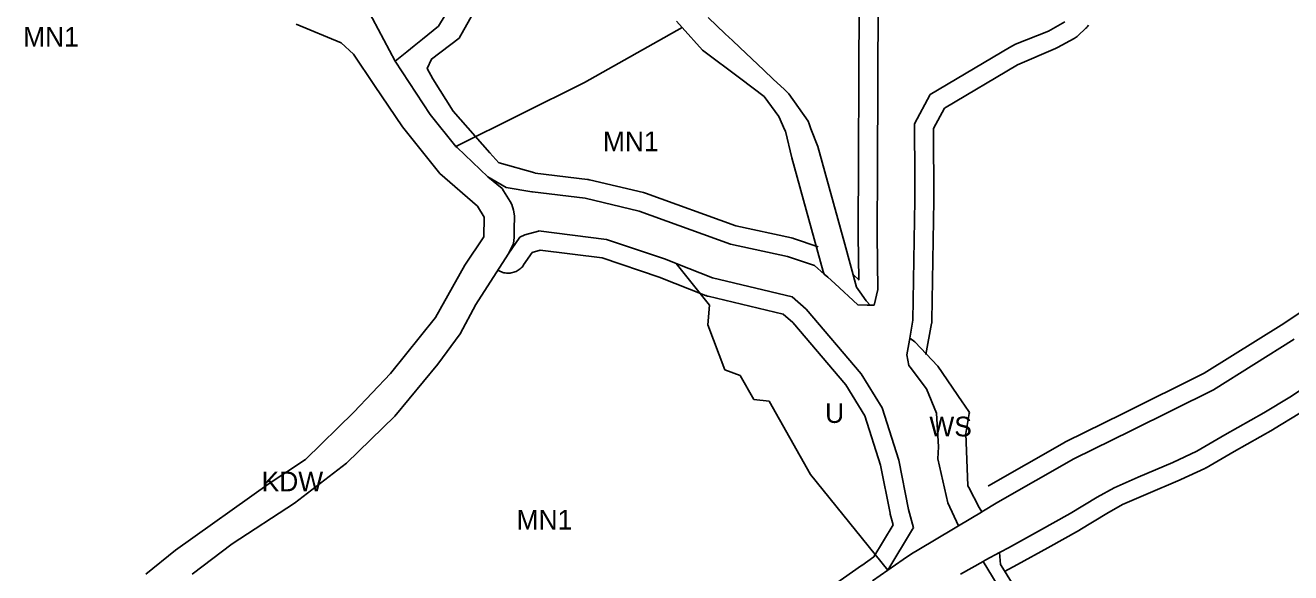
# Model space of a CAD drawing. Extents: x 7435758 to 7439981, y 5550649 to 5554049.
# Drawn here: x 7437108.7 to 7437442.5, y 5551598.7 to 5551743.2 of the extents above; entities that cross this region are included whole.
import ezdxf

# ---------------------------------------------------------------- set-up
doc = ezdxf.new("R2010")
doc.units = 0
for name, color, linetype in [('linie_rozgraniczające', 7, 'Continuous'), ('linie_zabudowy_nieprzekraczalne', 7, 'Continuous'), ('oznaczenia_przeznaczen', 7, 'Continuous')]:
    doc.layers.add(name, color=color, linetype=linetype)

msp = doc.modelspace()

# ---------------------------------------------------------------- linework, layer by layer
at = {"layer": 'linie_rozgraniczające'}
for p, q in [((7437198.86, 5551747.75), (7437206.28, 5551733.7)), ((7437217.69, 5551742.95), (7437221.24, 5551748.69)), ((7437333.66, 5551749.77), (7437333.45, 5551705.87)), ((7437293.36, 5551740.92), (7437288.8, 5551745.24)), ((7437180.18, 5551743.49), (7437192.05, 5551738.53)), ((7437213.5, 5551739.48), (7437217.69, 5551742.95)), ((7437256.26, 5551728.09), (7437281.97, 5551742.54)), ((7437280.47, 5551744.21), (7437281.97, 5551742.54)), ((7437281.97, 5551742.54), (7437287.32, 5551736.59)), ((7437369.87, 5551738.15), (7437378.55, 5551741.64)), ((7437378.55, 5551741.64), (7437382.91, 5551744.04)), ((7437192.05, 5551738.53), (7437195.28, 5551735.55)), ((7437209.36, 5551736.12), (7437211.34, 5551737.73)), ((7437211.34, 5551737.73), (7437213.5, 5551739.48)), ((7437295.25, 5551739.13), (7437293.36, 5551740.92)), ((7437297.16, 5551737.33), (7437295.25, 5551739.13)), ((7437368.28, 5551737.25), (7437369.87, 5551738.15)), ((7437195.28, 5551735.55), (7437200.81, 5551727.22)), ((7437206.28, 5551733.7), (7437209.36, 5551736.12)), ((7437287.32, 5551736.59), (7437297.41, 5551729.02)), ((7437303.53, 5551731.3), (7437297.16, 5551737.33)), ((7437347.38, 5551724.87), (7437368.28, 5551737.25)), ((7437206.28, 5551733.7), (7437215.51, 5551719.65)), ((7437306, 5551728.97), (7437303.53, 5551731.3)), ((7437222.33, 5551711.2), (7437256.26, 5551728.09)), ((7437297.41, 5551729.02), (7437303.64, 5551724.33)), ((7437308.95, 5551726.17), (7437306, 5551728.97)), ((7437200.81, 5551727.22), (7437208.25, 5551716.37)), ((7437310.1, 5551725.09), (7437308.95, 5551726.17)), ((7437315.18, 5551717.81), (7437310.1, 5551725.09)), ((7437343.26, 5551717.18), (7437347.38, 5551724.87)), ((7437303.64, 5551724.33), (7437307.51, 5551719.07)), ((7437215.51, 5551719.65), (7437222.33, 5551711.2)), ((7437307.51, 5551719.07), (7437309.08, 5551715.51)), ((7437315.44, 5551717.16), (7437315.18, 5551717.81)), ((7437208.25, 5551716.37), (7437218.08, 5551704.06)), ((7437309.08, 5551715.51), (7437309.23, 5551715.18)), ((7437309.23, 5551715.18), (7437310.86, 5551708.2)), ((7437315.94, 5551715.86), (7437315.44, 5551717.16)), ((7437317.77, 5551711.13), (7437315.94, 5551715.86)), ((7437343.34, 5551702.98), (7437343.26, 5551717.18)), ((7437222.6, 5551710.86), (7437222.33, 5551711.2)), ((7437324.84, 5551685.4), (7437317.77, 5551711.13)), ((7437230.7, 5551703.15), (7437222.6, 5551710.86)), ((7437310.86, 5551708.2), (7437319.17, 5551678.19)), ((7437333.45, 5551705.87), (7437333.36, 5551687.76)), ((7437218.08, 5551704.06), (7437228.03, 5551695.39)), ((7437230.7, 5551703.15), (7437234.49, 5551700.1)), ((7437235.52, 5551700.32), (7437230.7, 5551703.15)), ((7437343.37, 5551696.97), (7437343.34, 5551702.98)), ((7437234.49, 5551700.1), (7437234.89, 5551699.5)), ((7437234.89, 5551699.5), (7437236.62, 5551696.62)), ((7437242.31, 5551699.24), (7437235.52, 5551700.32)), ((7437242.54, 5551699.2), (7437242.31, 5551699.24)), ((7437256.39, 5551697.51), (7437242.54, 5551699.2)), ((7437228.03, 5551695.39), (7437229.76, 5551692.5)), ((7437236.62, 5551696.62), (7437237.02, 5551695.86)), ((7437237.02, 5551695.86), (7437237.53, 5551694.38)), ((7437237.53, 5551694.38), (7437237.75, 5551692.83)), ((7437270.65, 5551694.13), (7437256.39, 5551697.51)), ((7437342.85, 5551665.33), (7437343.37, 5551696.97)), ((7437229.76, 5551692.5), (7437229.66, 5551687.29)), ((7437237.76, 5551692.35), (7437237.71, 5551689.79)), ((7437237.75, 5551692.83), (7437237.76, 5551692.35)), ((7437294.72, 5551685.4), (7437270.65, 5551694.13)), ((7437237.71, 5551689.79), (7437237.66, 5551687.14)), ((7437239.19, 5551687.25), (7437240.52, 5551687.83)), ((7437240.52, 5551687.83), (7437244.05, 5551688.87)), ((7437244.05, 5551688.87), (7437244.09, 5551688.88)), ((7437244.09, 5551688.88), (7437262.03, 5551686.67)), ((7437333.36, 5551687.76), (7437333.6, 5551673.42)), ((7437229.66, 5551687.29), (7437224.64, 5551679.82)), ((7437236.06, 5551682.75), (7437239.19, 5551687.25)), ((7437237.47, 5551685.53), (7437236.06, 5551682.75)), ((7437237.66, 5551687.14), (7437237.47, 5551685.53)), ((7437262.03, 5551686.67), (7437277.6, 5551681.43)), ((7437309.75, 5551682.17), (7437294.72, 5551685.4)), ((7437327.95, 5551674.09), (7437324.84, 5551685.4)), ((7437227.53, 5551669.44), (7437236.06, 5551682.75)), ((7437277.6, 5551681.43), (7437280.43, 5551680.31)), ((7437316.85, 5551679.75), (7437309.75, 5551682.17)), ((7437224.64, 5551679.82), (7437216.9, 5551666.02)), ((7437280.43, 5551680.31), (7437289.18, 5551669.33)), ((7437280.43, 5551680.31), (7437289.99, 5551676.51)), ((7437319.46, 5551677.45), (7437316.85, 5551679.75)), ((7437319.17, 5551678.19), (7437319.46, 5551677.45)), ((7437289.99, 5551676.51), (7437310.98, 5551671.49)), ((7437319.46, 5551677.45), (7437320.36, 5551676.65)), ((7437320.36, 5551676.65), (7437322.24, 5551675)), ((7437322.24, 5551675), (7437328.34, 5551669.37)), ((7437310.98, 5551671.49), (7437314.72, 5551668.25)), ((7437328.86, 5551672.79), (7437327.95, 5551674.09)), ((7437330.51, 5551670.46), (7437328.86, 5551672.79)), ((7437333.6, 5551673.42), (7437332.64, 5551669.32)), ((7437223.43, 5551661.75), (7437227.53, 5551669.44)), ((7437289.18, 5551669.33), (7437288.76, 5551664.07)), ((7437314.72, 5551668.25), (7437329.19, 5551651.22)), ((7437328.34, 5551669.37), (7437330.77, 5551669.34)), ((7437331.52, 5551669.33), (7437330.51, 5551670.46)), ((7437330.77, 5551669.34), (7437331.52, 5551669.33)), ((7437332.64, 5551669.32), (7437331.52, 5551669.33)), ((7437216.9, 5551666.02), (7437205.05, 5551651.28)), ((7437341.98, 5551660.56), (7437342.85, 5551665.33)), ((7437217.53, 5551653.73), (7437223.43, 5551661.75)), ((7437288.76, 5551664.07), (7437293.23, 5551652.27)), ((7437341.89, 5551660.07), (7437341.19, 5551656.23)), ((7437341.98, 5551660.56), (7437341.89, 5551660.07)), ((7437343.36, 5551659.6), (7437341.98, 5551660.56)), ((7437349.43, 5551653.22), (7437343.36, 5551659.6)), ((7437443.4, 5551660.3), (7437422.12, 5551647)), ((7437341.19, 5551656.23), (7437341.73, 5551653.37)), ((7437205.05, 5551651.28), (7437195.36, 5551641.03)), ((7437206.16, 5551640.05), (7437217.53, 5551653.73)), ((7437293.23, 5551652.27), (7437297.28, 5551650.76)), ((7437329.19, 5551651.22), (7437334.75, 5551642.19)), ((7437341.73, 5551653.37), (7437342.07, 5551652.93)), ((7437342.07, 5551652.93), (7437342.09, 5551652.9)), ((7437342.09, 5551652.9), (7437346.45, 5551647.18)), ((7437355.85, 5551643.78), (7437349.43, 5551653.22)), ((7437442.25, 5551645.05), (7437455.22, 5551653.73)), ((7437297.28, 5551650.76), (7437300.9, 5551644.39)), ((7437300.9, 5551644.39), (7437304.91, 5551643.93)), ((7437346.45, 5551647.18), (7437349.04, 5551640.83)), ((7437422.12, 5551647), (7437400.48, 5551636.23)), ((7437435.36, 5551640.86), (7437442.25, 5551645.05)), ((7437195.36, 5551641.03), (7437182.64, 5551628.59)), ((7437304.91, 5551643.93), (7437315.78, 5551624.62)), ((7437334.75, 5551642.19), (7437339.15, 5551628.36)), ((7437356.44, 5551642.91), (7437355.85, 5551643.78)), ((7437357.73, 5551641.02), (7437356.44, 5551642.91)), ((7437357.68, 5551640.73), (7437357.73, 5551641.02)), ((7437193.44, 5551627.6), (7437206.16, 5551640.05)), ((7437349.04, 5551640.83), (7437349.58, 5551631.89)), ((7437356.75, 5551635.42), (7437357.68, 5551640.73)), ((7437425.1, 5551635.06), (7437435.36, 5551640.86)), ((7437357.3, 5551621.65), (7437356.75, 5551635.42)), ((7437400.48, 5551636.23), (7437385.3, 5551628.76)), ((7437417.69, 5551630.74), (7437425.1, 5551635.06)), ((7437349.58, 5551631.89), (7437349.38, 5551628.79)), ((7437182.64, 5551628.59), (7437173.04, 5551622.24)), ((7437179.73, 5551617.06), (7437193.44, 5551627.6)), ((7437339.15, 5551628.36), (7437341.71, 5551615.37)), ((7437349.38, 5551628.79), (7437352.01, 5551617.11)), ((7437385.3, 5551628.76), (7437365.21, 5551617.29)), ((7437402.23, 5551623.95), (7437411.37, 5551627.82)), ((7437411.37, 5551627.82), (7437417.69, 5551630.74)), ((7437315.78, 5551624.62), (7437336.26, 5551599.38)), ((7437173.04, 5551622.24), (7437148.34, 5551604.64)), ((7437357.55, 5551621.19), (7437357.3, 5551621.65)), ((7437360.31, 5551615.9), (7437357.55, 5551621.19)), ((7437391.43, 5551618.66), (7437395.88, 5551621.14)), ((7437395.88, 5551621.14), (7437402.23, 5551623.95)), ((7437384.27, 5551614.31), (7437391.43, 5551618.66)), ((7437163.32, 5551606.28), (7437179.73, 5551617.06)), ((7437341.71, 5551615.37), (7437342.95, 5551610.56)), ((7437352.01, 5551617.11), (7437354.83, 5551611.09)), ((7437354.83, 5551611.09), (7437360.88, 5551614.71)), ((7437361.02, 5551614.79), (7437360.31, 5551615.9)), ((7437360.88, 5551614.71), (7437361.02, 5551614.79)), ((7437365.21, 5551617.29), (7437361.02, 5551614.79)), ((7437375.99, 5551609.64), (7437384.27, 5551614.31)), ((7437353.54, 5551610.32), (7437354.83, 5551611.09)), ((7437342.73, 5551610.16), (7437336.26, 5551599.38)), ((7437342.95, 5551610.56), (7437342.73, 5551610.16)), ((7437344.42, 5551604.87), (7437353.54, 5551610.32)), ((7437368.02, 5551605.29), (7437375.99, 5551609.64)), ((7437148.34, 5551604.64), (7437140.56, 5551598.36)), ((7437152.75, 5551598.33), (7437163.32, 5551606.28)), ((7437342.42, 5551603.68), (7437344.42, 5551604.87)), ((7437365.64, 5551604.02), (7437366.06, 5551604.25)), ((7437366.06, 5551604.25), (7437368.02, 5551605.29)), ((7437336.26, 5551599.38), (7437340.3, 5551602.2)), ((7437340.3, 5551602.2), (7437342.42, 5551603.68)), ((7437355.37, 5551598.35), (7437361.33, 5551601.7)), ((7437361.88, 5551602.01), (7437361.33, 5551601.7)), ((7437361.33, 5551601.7), (7437366.52, 5551593.17)), ((7437362.07, 5551602.11), (7437361.88, 5551602.01)), ((7437365.63, 5551604.02), (7437362.07, 5551602.11)), ((7437365.89, 5551600.84), (7437365.63, 5551604.02)), ((7437365.63, 5551604.02), (7437365.64, 5551604.02)), ((7437336.26, 5551599.38), (7437332.17, 5551596.54)), ((7437366.07, 5551600.57), (7437365.89, 5551600.84)), ((7437379.39, 5551579.55), (7437366.07, 5551600.57))]:
    msp.add_line(p, q, dxfattribs=at)
at = {"layer": 'linie_zabudowy_nieprzekraczalne'}
for points in [[(7437327.25, 5551677.18), (7437328.56, 5551675.97), (7437328.36, 5551687.67), (7437328.36, 5551687.78), (7437328.66, 5551749.73), (7437328.02, 5551782.17), (7437328.02, 5551782.39), (7437328.03, 5551782.45), (7437329.33, 5551819.31), (7437328.28, 5551829.75), (7437325.32, 5551839.64), (7437310.51, 5551880.32), (7437291.66, 5551930.23), (7437291.66, 5551930.26), (7437278.98, 5551964.3), (7437278.97, 5551964.34), (7437266.89, 5551997.74), (7437262.43, 5551995.85), (7437262.4, 5551995.84), (7437197.61, 5551968.8)], [(7437229.18, 5551750.51), (7437223.17, 5551739.77), (7437215.85, 5551734.22), (7437214.76, 5551731.79), (7437216.25, 5551728.99), (7437221.59, 5551720.51), (7437231.29, 5551709.54), (7437233.64, 5551706.89), (7437233.73, 5551706.86), (7437243.09, 5551704.18), (7437243.24, 5551704.16), (7437257, 5551702.47), (7437257.17, 5551702.45), (7437257.49, 5551702.39), (7437257.54, 5551702.37), (7437271.8, 5551699), (7437272.06, 5551698.93), (7437272.35, 5551698.83), (7437296.1, 5551690.21), (7437310.8, 5551687.06), (7437310.85, 5551687.05), (7437311.17, 5551686.96), (7437311.37, 5551686.9), (7437317.83, 5551684.7)], [(7437346.28, 5551656.3), (7437347.77, 5551664.43), (7437347.79, 5551664.55), (7437347.83, 5551664.88), (7437347.85, 5551665.2), (7437347.85, 5551665.25), (7437348.37, 5551696.89), (7437348.37, 5551697), (7437348.27, 5551715.94), (7437351.13, 5551721.28), (7437370.43, 5551732.71), (7437380.41, 5551737), (7437380.65, 5551737.1), (7437380.94, 5551737.25), (7437380.97, 5551737.26), (7437385.32, 5551739.66), (7437385.58, 5551739.82), (7437385.85, 5551740), (7437386.11, 5551740.2), (7437386.3, 5551740.37), (7437388.45, 5551742.35), (7437388.5, 5551742.4), (7437388.73, 5551742.64), (7437388.94, 5551742.88), (7437389.14, 5551743.15), (7437389.15, 5551743.17)], [(7437311.74, 5551588.29), (7437329.3, 5551600.63), (7437329.32, 5551600.64), (7437332.52, 5551602.87), (7437337.59, 5551611.32), (7437336.87, 5551614.12), (7437336.85, 5551614.19), (7437336.81, 5551614.4), (7437334.3, 5551627.12), (7437330.18, 5551640.09), (7437325.14, 5551648.28), (7437311.16, 5551664.72), (7437308.63, 5551666.91), (7437288.83, 5551671.65), (7437288.58, 5551671.71), (7437288.27, 5551671.82), (7437288.15, 5551671.86), (7437275.88, 5551676.73), (7437260.91, 5551681.77), (7437244.51, 5551683.79), (7437242.45, 5551683.19), (7437240.17, 5551679.9), (7437240.15, 5551679.87), (7437239.95, 5551679.61), (7437239.74, 5551679.36), (7437239.51, 5551679.13), (7437239.26, 5551678.91), (7437239.01, 5551678.71), (7437238.73, 5551678.52), (7437238.45, 5551678.36), (7437238.16, 5551678.21), (7437237.86, 5551678.08), (7437237.55, 5551677.98), (7437237.24, 5551677.89), (7437236.91, 5551677.82), (7437236.59, 5551677.78), (7437236.26, 5551677.75), (7437235.94, 5551677.75), (7437235.61, 5551677.77), (7437235.29, 5551677.81), (7437234.96, 5551677.87), (7437234.65, 5551677.95), (7437234.34, 5551678.06), (7437234.03, 5551678.18), (7437233.74, 5551678.32), (7437233.45, 5551678.48), (7437233.36, 5551678.54)], [(7437467.33, 5551682.35), (7437440.68, 5551664.5), (7437419.67, 5551651.37), (7437398.25, 5551640.71), (7437383.09, 5551633.25), (7437382.91, 5551633.15), (7437382.82, 5551633.1), (7437362.73, 5551621.63), (7437362.65, 5551621.58)], [(7437444.85, 5551640.78), (7437437.96, 5551636.59), (7437437.82, 5551636.51), (7437427.59, 5551630.72), (7437420.21, 5551626.42), (7437420.08, 5551626.34), (7437419.79, 5551626.2), (7437419.78, 5551626.2), (7437413.47, 5551623.28), (7437413.32, 5551623.22), (7437404.22, 5551619.37), (7437398.11, 5551616.67), (7437393.95, 5551614.34), (7437386.86, 5551610.03), (7437386.72, 5551609.96), (7437378.45, 5551605.28), (7437378.39, 5551605.25), (7437370.41, 5551600.9), (7437370.38, 5551600.88), (7437366.95, 5551599.05)]]:
    msp.add_lwpolyline(points, dxfattribs=at)

# ---------------------------------------------------------------- texts
at = {"layer": 'oznaczenia_przeznaczen'}
for s, p in [('MN1', (7437108.18, 5551737.52)), ('MN1', (7437261.08, 5551709.92)), ('U', (7437319.67, 5551638.23)), ('WS', (7437347.17, 5551634.68)), ('KDW', (7437171.08, 5551620.18)), ('MN1', (7437238.3, 5551610.07))]:
    msp.add_text(s, height=5.2, dxfattribs=at).set_placement(p)

doc.saveas('drawing.dxf')
